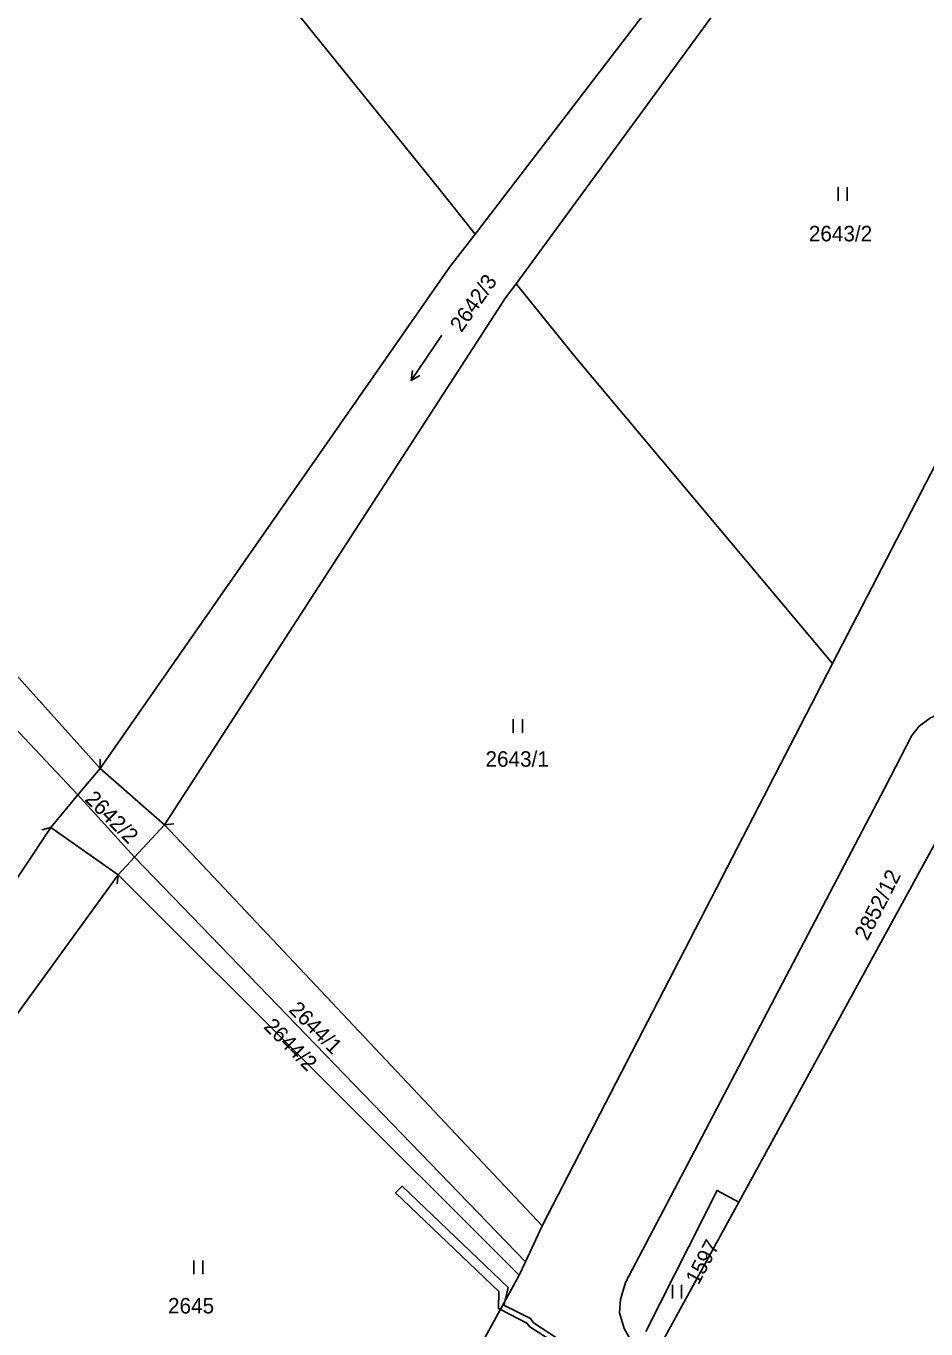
# Model space of a CAD drawing. Extents: x -562167 to -556918, y -1077891 to -1070763.
# Drawn here: x -560237.8 to -560139.1, y -1075721.8 to -1075578.8 of the extents above; entities that cross this region are included whole.
import ezdxf

# ---------------------------------------------------------------- set-up
doc = ezdxf.new("R2010")
doc.units = 0
for name, color, linetype in [('Hranice parcel', 7, 'Continuous'), ('Parcelní čísla', 7, 'Continuous'), ('Vnitřní kresba', 7, 'Continuous'), ('Věcná břemena k části', 7, 'Continuous'), ('Značky kultur', 7, 'Continuous')]:
    doc.layers.add(name, color=color, linetype=linetype)

msp = doc.modelspace()

# ---------------------------------------------------------------- linework, layer by layer
at = {"layer": 'Hranice parcel'}
for p, q in [((-560188.52, -1075601.62), (-560151.27, -1075553.04)), ((-560147.85, -1075557.59), (-560184.02, -1075607.07)), ((-560149.3, -1075648.77), (-560119.89, -1075591.8)), ((-560181.15, -1075710.48), (-560149.3, -1075648.77)), ((-560229.67, -1075660.27), (-560232.11, -1075663.19)), ((-560222.59, -1075666.47), (-560229.67, -1075660.27)), ((-560232.11, -1075663.19), (-560235.08, -1075666.76)), ((-560225.91, -1075670.03), (-560232.11, -1075663.19)), ((-560225.91, -1075670.03), (-560222.59, -1075666.47)), ((-560222.59, -1075666.47), (-560181.15, -1075710.48)), ((-560136.31, -1075665.35), (-560159.58, -1075707.9)), ((-560235.08, -1075666.76), (-560263.43, -1075709.3)), ((-560227.7, -1075671.95), (-560225.91, -1075670.03)), ((-560225.91, -1075670.03), (-560183, -1075714.44)), ((-560258.86, -1075714.73), (-560227.7, -1075671.95)), ((-560183.67, -1075715.89), (-560227.7, -1075671.95)), ((-560159.58, -1075707.9), (-560168.31, -1075723.85)), ((-560183, -1075714.44), (-560181.15, -1075710.48)), ((-560183.67, -1075715.89), (-560183, -1075714.44)), ((-560210.52, -1075764.64), (-560183.67, -1075715.89))]:
    msp.add_line(p, q, dxfattribs=at)
for points in [[(-560188.52, -1075601.62), (-560192.37, -1075596.82), (-560215.41, -1075568.21), (-560235.73, -1075544.23), (-560276.04, -1075495.75), (-560314.38, -1075451.59), (-560345.12, -1075399.6), (-560355.52, -1075363.91), (-560365.71, -1075326.83), (-560373.76, -1075302.38), (-560402.21, -1075227.6), (-560423.47, -1075185.99), (-560456.13, -1075131.42), (-560469.14, -1075107.07)], [(-560229.67, -1075660.27), (-560191.28, -1075605.23), (-560188.52, -1075601.62)], [(-560222.59, -1075666.47), (-560185.17, -1075608.63), (-560184.02, -1075607.07)], [(-560149.3, -1075648.77), (-560177.38, -1075615.27), (-560184.02, -1075607.07)], [(-560277.18, -1075611.34), (-560274.09, -1075608.51), (-560256.28, -1075631.3), (-560248.53, -1075639.27), (-560229.67, -1075660.27)], [(-560232.11, -1075663.19), (-560256.71, -1075637.07), (-560277.18, -1075611.34)], [(-560170.71, -1075723.93), (-560171.34, -1075723.24), (-560172.18, -1075721.74), (-560172.67, -1075720.03), (-560172.57, -1075718.58), (-560172.02, -1075716.72), (-560164.42, -1075702.22), (-560143.59, -1075662.47), (-560140.58, -1075656.65), (-560139.8, -1075655.62), (-560138.56, -1075654.71), (-560136.89, -1075653.98), (-560134.96, -1075653.67), (-560132.8, -1075653.95), (-560130.94, -1075654.25)], [(-560159.58, -1075707.9), (-560161.95, -1075706.6), (-560169.77, -1075722.07)]]:
    msp.add_lwpolyline(points, dxfattribs=at)
at = {"layer": 'Vnitřní kresba'}
for p, q in [((-560229.67, -1075659.27), (-560229.67, -1075660.27)), ((-560221.59, -1075666.37), (-560222.59, -1075666.47)), ((-560236.05, -1075667), (-560235.08, -1075666.76)), ((-560235.08, -1075666.76), (-560227.7, -1075671.95)), ((-560227.79, -1075672.95), (-560227.7, -1075671.95))]:
    msp.add_line(p, q, dxfattribs=at)
at = {"layer": 'Věcná břemena k části'}
for points in [[(-560185.75, -1075719.67), (-560185.26, -1075718.78), (-560184.91, -1075717.26), (-560196.54, -1075706.14), (-560197.24, -1075706.86), (-560185.93, -1075717.68), (-560185.96, -1075719.56)], [(-560185.26, -1075718.78), (-560185.75, -1075719.67), (-560182.86, -1075721.15), (-560182.53, -1075721.57), (-560174.05, -1075727), (-560173.46, -1075727.12), (-560172.47, -1075727.43), (-560182.11, -1075721.13), (-560182.46, -1075720.67), (-560185.36, -1075719.2)]]:
    msp.add_lwpolyline(points, close=True, dxfattribs=at)
at = {"layer": 'Značky kultur'}
for p, q in [((-560148.68, -1075597.97), (-560148.68, -1075596.47)), ((-560147.68, -1075597.97), (-560147.68, -1075596.47)), ((-560192.18, -1075612.71), (-560195.53, -1075617.69)), ((-560195.53, -1075617.69), (-560195.4, -1075616.6)), ((-560195.53, -1075617.69), (-560194.57, -1075617.16)), ((-560184.33, -1075656.36), (-560184.33, -1075654.86)), ((-560183.33, -1075656.36), (-560183.33, -1075654.86)), ((-560219.4, -1075715.78), (-560219.4, -1075714.28)), ((-560218.4, -1075715.78), (-560218.4, -1075714.28)), ((-560166.87, -1075718.46), (-560166.87, -1075716.96)), ((-560165.87, -1075718.46), (-560165.87, -1075716.96))]:
    msp.add_line(p, q, dxfattribs=at)

# ---------------------------------------------------------------- texts
at = {"layer": 'Parcelní čísla'}
for s, p in [('2643/2', (-560151.9, -1075602.42)), ('2643/1', (-560187.38, -1075660.09)), ('2645', (-560222.22, -1075720.1))]:
    msp.add_text(s, height=1.7, dxfattribs=at).set_placement(p)
for s, rotation, p in [('2642/3', 55, (-560190.02, -1075612.51)), ('2642/2', 315, (-560231.43, -1075663.75)), ('2852/12', 63, (-560145.47, -1075679.28)), ('2644/1', 315, (-560209.06, -1075686.87)), ('2644/2', 315, (-560211.82, -1075688.71)), ('1597', 62, (-560164.02, -1075717.07))]:
    msp.add_text(s, height=1.7, rotation=rotation, dxfattribs=at).set_placement(p)

doc.saveas('drawing.dxf')
